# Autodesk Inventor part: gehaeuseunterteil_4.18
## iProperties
Shininess: 64.0
Length Units: 11269
Angle Units: 11279
Time Units: 11290
Mass Units: 11283
Length Display Precision: 3
Angle Display Precision: 2
Compacted: True
Part Number: gehaeuseunterteil_4.18
Document SubType Name: Modeling
Created: 2005-01
Material: Standard
Density: 0.0
Volumn: 0.0
Area: 0.0
PropertySet Name: Model Information
Control State: 0
Master: False
Checked Out: False
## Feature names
1. Extrusion1
2. Extrusion2
3. Rundung1 [Fillet]
4. Extrusion3
5. Extrusion4
6. Extrusion5
7. Rundung2 [Fillet]
8. Rundung3 [Fillet]
9. Rundung4 [Fillet]
10. Extrusion6
11. Spiegeln1 [Mirror]
12. Rundung5 [Fillet]
13. Extrusion7
14. Rundung6 [Fillet]
15. Extrusion8
16. Spiegeln2 [Mirror]
17. Rundung7 [Fillet]
18. Wandstärke1
